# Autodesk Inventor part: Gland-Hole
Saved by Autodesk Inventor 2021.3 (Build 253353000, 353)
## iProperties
Created: 2023-07
Part Number: Gland-Hole
Material: Generic
Document SubType Name: Modeling
Designer: AdminForWorker
Density: 1 g/cm^3
Appearance: Default
Title: Gland-Hole
Author: AdminForWorker
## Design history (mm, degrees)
feature "Gland-Hole"
body "Solid1"
